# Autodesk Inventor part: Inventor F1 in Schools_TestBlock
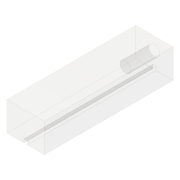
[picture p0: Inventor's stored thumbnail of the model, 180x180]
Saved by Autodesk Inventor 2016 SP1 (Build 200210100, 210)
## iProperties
Created: 2015-12
Part Number: Inventor F1 in Schools_TestBlock
Material: Polystyrene
Document SubType Name: Modeling
Designer: Autodesk Inc.
Density: 1.021 g/cm^3
Appearance: Polycarbonate - Clear
Author: Autodesk Inc
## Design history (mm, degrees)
sketch "Sketch1"
  geometry: L1 (0, 0)-(-65, 0); L2 (-65, 0)-(-65, -223); L3 (-65, -223)-(0, -223); L4 (0, -223)-(0, 0)
  constraints: 8 end point, 2 parallel, 1 horizontal, 1 perpendicular
  dimensions: "d0" = 65 distance of L3.end L2.end; "d1" = 223 distance of L2.end L1.end
extrude "Extrusion1" new body sketch "Sketch1" distance "d2" = 50; taper "d3" = 0 deg
sketch "Sketch2"
  geometry: L1 (0, 0)-(65, 0) reference; L2 (65, 0)-(65, 50) reference; C1 r 9.5 at (32.5, 29)
  constraints: 1 centre point
  dimensions: "d4" = 19 diameter of C1; "d5" = 29 distance from line of L1 C1.centre; "d6" = 32.5 distance from line of L2 C1.centre
extrude "Extrusion2" cut sketch "Sketch2" distance "d7" = 50; taper "d8" = 0 deg
sketch "Sketch3"
  geometry: L1 (0, 0)-(65, 0) reference; L2 (29.5, 0)-(35.5, 0); L3 (35.5, 0)-(35.5, 6); L4 (35.5, 6)-(29.5, 6); L5 (29.5, 6)-(29.5, 0); 2 further points
  constraints: 8 end point, 2 midpoint, 2 parallel, 1 collinear, 1 horizontal, 1 perpendicular, 1 vertical alignment
  dimensions: "d11" = 6 distance of L4.end L3.end; "d12" = 6 distance of L3.end L2.end
extrude "Extrusion3" cut sketch "Sketch3" stored distance "d13" = 10; taper "d14" = 0 deg
body "Solid1"
